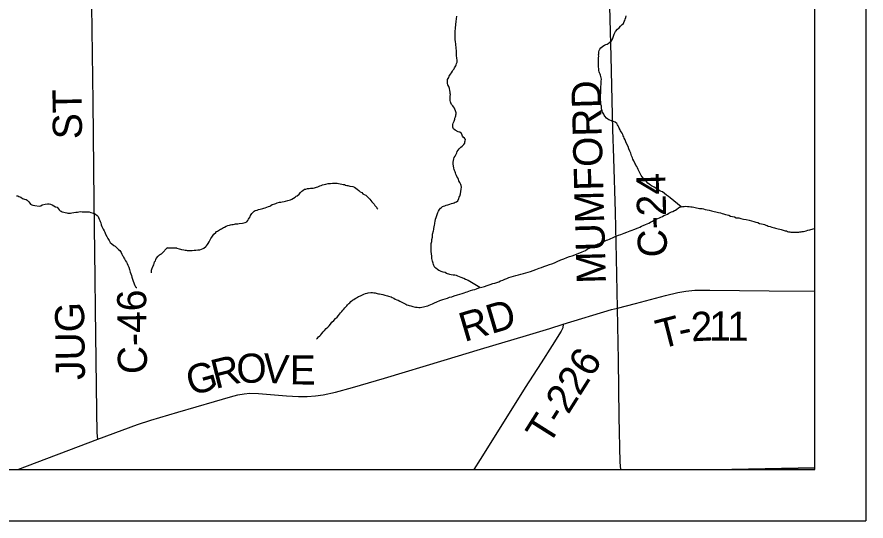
# Model space of a CAD drawing. Extents: x 0 to 34, y 0 to 22.
# Drawn here: x 7.606 to 9.262, y 14.238 to 15.221 of the extents above; entities that cross this region are included whole.
import ezdxf

# ---------------------------------------------------------------- set-up
doc = ezdxf.new("R2010")
doc.units = 0
for name, color, linetype in [('GM_X_Adjacent_County', 7, 'Continuous'), ('GM_X_County', 7, 'Continuous'), ('GM_X_County_Road', 7, 'Continuous'), ('GM_X_County_Road_Text', 7, 'Continuous'), ('GM_X_Minor_River', 7, 'Continuous'), ('GM_X_Township', 7, 'Continuous'), ('GM_X_Township_Road', 7, 'Continuous'), ('GM_X_Township_Road_Text', 7, 'Continuous'), ('SH_Data', 7, 'Continuous')]:
    doc.layers.add(name, color=color, linetype=linetype)

msp = doc.modelspace()

# ---------------------------------------------------------------- linework, layer by layer
at = {"layer": 'GM_X_Adjacent_County'}
msp.add_line((9.1622, 14.342), (9.0003, 14.3385), dxfattribs=at)
msp.add_lwpolyline([(9.0003, 14.3385), (9.1622, 14.3385), (9.1622, 14.342)], dxfattribs=at)
at = {"layer": 'GM_X_County'}
msp.add_line((9.0003, 14.3385), (9.1622, 14.342), dxfattribs=at)
msp.add_lwpolyline([(9.1622, 14.342), (9.1622, 21.1385), (2.3622, 21.1385), (2.3622, 14.3385), (9.0003, 14.3385)], dxfattribs=at)
at = {"layer": 'GM_X_County_Road'}
for points in [[(8.7838, 14.3385), (8.7824, 14.3532), (8.7805, 14.4411), (8.7792, 14.5521), (8.7772, 14.6534), (8.7751, 14.7509), (8.773, 14.8406), (8.7698, 14.9457), (8.7683, 15.0013), (8.7648, 15.1439), (8.7597, 15.3395), (8.7581, 15.4244), (8.756, 15.5234), (8.7553, 15.5899), (8.7512, 15.8644), (8.748, 16.0625), (8.7455, 16.2486), (8.7445, 16.3137), (8.7438, 16.3585)], [(7.7638, 14.3975), (7.7622, 14.4101), (7.7615, 14.4524), (7.7594, 14.6515), (7.7585, 14.7123), (7.7568, 14.8609), (7.7544, 15.0554), (7.7522, 15.2423), (7.7514, 15.2867), (7.7502, 15.4013), (7.7494, 15.4167)], [(7.6075, 14.3385), (7.7638, 14.3975)]]:
    msp.add_lwpolyline(points, dxfattribs=at)
at = {"layer": 'GM_X_Minor_River'}
for points in [[(8.4647, 14.9583), (8.4665, 14.9614), (8.4683, 14.9641), (8.4717, 14.9672), (8.4743, 14.9692), (8.4773, 14.9723), (8.4791, 14.975), (8.4794, 14.9773), (8.4801, 14.9796), (8.4809, 14.9823), (8.4785, 14.9845), (8.4762, 14.9868), (8.4746, 14.9886), (8.4742, 14.9905), (8.4726, 14.9939), (8.4699, 14.9961), (8.4664, 14.9968), (8.4603, 15.0001), (8.4572, 15.0031), (8.456, 15.0061), (8.4559, 15.0091), (8.4559, 15.011), (8.4565, 15.0141), (8.4584, 15.018), (8.4598, 15.0214), (8.4601, 15.0233), (8.4612, 15.026), (8.4616, 15.0279), (8.4619, 15.0298), (8.4622, 15.0321), (8.4622, 15.034), (8.4617, 15.0359), (8.4613, 15.0382), (8.4601, 15.0412), (8.4589, 15.0431), (8.457, 15.0457), (8.4558, 15.0476), (8.4534, 15.0502), (8.4518, 15.0536), (8.4514, 15.0555), (8.451, 15.0578), (8.4509, 15.0604), (8.4509, 15.0631), (8.4508, 15.0665), (8.4511, 15.0696), (8.451, 15.0715), (8.4506, 15.0741), (8.4501, 15.0775), (8.4493, 15.0817), (8.4481, 15.0855), (8.4465, 15.0889), (8.4453, 15.0911), (8.4455, 15.0988), (8.447, 15.1011), (8.448, 15.103), (8.4491, 15.1053), (8.4502, 15.1072), (8.4517, 15.1095), (8.4532, 15.1122), (8.455, 15.1153), (8.4568, 15.1177), (8.4583, 15.1196), (8.4594, 15.1215), (8.4605, 15.1235), (8.462, 15.1258), (8.4623, 15.1277), (8.4634, 15.1304), (8.4641, 15.1327), (8.4644, 15.135), (8.4644, 15.1369), (8.4639, 15.1403), (8.4635, 15.1422), (8.4631, 15.1444), (8.463, 15.1475), (8.4629, 15.1502), (8.4628, 15.1555), (8.4627, 15.1597), (8.4618, 15.1688), (8.4613, 15.1726), (8.4608, 15.1768), (8.4604, 15.1802), (8.4603, 15.1832), (8.4602, 15.1866), (8.4605, 15.1924), (8.4611, 15.1992), (8.462, 15.2061), (8.4627, 15.2118), (8.4633, 15.2175), (8.4636, 15.2225)], [(8.7409, 15.1529), (8.7412, 15.1556), (8.7427, 15.1583), (8.7449, 15.161), (8.7487, 15.1638), (8.7517, 15.1657), (8.7543, 15.1673), (8.7569, 15.1681), (8.7588, 15.1693), (8.7622, 15.1717), (8.7648, 15.1737), (8.7666, 15.176), (8.7681, 15.1798), (8.7691, 15.1833), (8.7698, 15.1852), (8.7706, 15.1871), (8.772, 15.1898), (8.7735, 15.1925), (8.7772, 15.1968), (8.7802, 15.1999), (8.7831, 15.203), (8.7861, 15.2061), (8.7887, 15.2084), (8.7902, 15.2119), (8.7913, 15.2138), (8.7923, 15.2169), (8.7934, 15.22), (8.7941, 15.223)], [(8.9011, 14.8508), (8.8798, 14.8686), (8.8763, 14.8712), (8.8724, 14.8738), (8.8686, 14.8768), (8.8647, 14.8797), (8.8601, 14.8815), (8.8574, 14.883), (8.8547, 14.8848), (8.8516, 14.887), (8.8485, 14.8893), (8.8458, 14.8903), (8.8435, 14.8918), (8.8412, 14.8933), (8.8389, 14.8947), (8.8361, 14.897), (8.8334, 14.9), (8.8299, 14.9033), (8.8276, 14.9063), (8.8252, 14.9093), (8.8232, 14.9119), (8.8185, 14.9209), (8.8173, 14.9236), (8.8161, 14.927), (8.8145, 14.9296), (8.8129, 14.9319), (8.8121, 14.9341), (8.8109, 14.936), (8.8089, 14.9405), (8.8073, 14.9435), (8.8061, 14.9465), (8.8045, 14.9503), (8.8029, 14.9552), (8.8009, 14.9594), (8.7992, 14.9639), (8.7976, 14.9684), (8.7956, 14.9726), (8.7936, 14.9775), (8.792, 14.9813), (8.7904, 14.9843), (8.7892, 14.9869), (8.788, 14.9892), (8.7872, 14.9918), (8.786, 14.9941), (8.7844, 14.9967), (8.7832, 14.999), (8.782, 15.0008), (8.7804, 15.0042), (8.7796, 15.0061), (8.7784, 15.0084), (8.7773, 15.0106), (8.7761, 15.0129), (8.7726, 15.0158), (8.7691, 15.0173), (8.7657, 15.0184), (8.7622, 15.0194), (8.7603, 15.0205), (8.758, 15.0216), (8.7557, 15.0238), (8.7525, 15.0272), (8.7513, 15.0295), (8.7502, 15.0313), (8.7478, 15.0355), (8.7473, 15.0377), (8.7465, 15.0396), (8.7461, 15.0415), (8.7457, 15.0449), (8.7456, 15.0468), (8.7452, 15.0491), (8.7447, 15.0518), (8.7443, 15.0548), (8.7442, 15.0594), (8.7437, 15.0635), (8.744, 15.0681), (8.7443, 15.0731), (8.7445, 15.0773), (8.7444, 15.0815), (8.7447, 15.0853), (8.745, 15.0891), (8.7453, 15.0921), (8.7453, 15.0959), (8.7456, 15.0994), (8.7451, 15.102), (8.7447, 15.1047), (8.7439, 15.1073), (8.743, 15.1096), (8.7422, 15.1119), (8.7414, 15.1141), (8.741, 15.1168), (8.7405, 15.1198), (8.7401, 15.1236), (8.74, 15.1278), (8.7399, 15.132), (8.7402, 15.1362), (8.7401, 15.1388), (8.74, 15.1415), (8.7404, 15.1442), (8.7403, 15.1468), (8.7406, 15.1491), (8.7406, 15.151), (8.7409, 15.1529)], [(8.5085, 14.6935), (8.4856, 14.7072), (8.4833, 14.7083), (8.4806, 14.7093), (8.4772, 14.7108), (8.4722, 14.7133), (8.4687, 14.7144), (8.466, 14.7155), (8.4633, 14.7166), (8.4599, 14.7173), (8.4565, 14.7176), (8.453, 14.7182), (8.4504, 14.7186), (8.4435, 14.7207), (8.4408, 14.7225), (8.4369, 14.7232), (8.435, 14.7239), (8.4331, 14.725), (8.4308, 14.7261), (8.4285, 14.7268), (8.4258, 14.7287), (8.4227, 14.7309), (8.4208, 14.7324), (8.4191, 14.7361), (8.4183, 14.7384), (8.4175, 14.7407), (8.4163, 14.7448), (8.4155, 14.7475), (8.415, 14.7498), (8.4149, 14.7547), (8.4144, 14.7593), (8.414, 14.7638), (8.4135, 14.7672), (8.4134, 14.7707), (8.4134, 14.7733), (8.4137, 14.7756), (8.414, 14.779), (8.4147, 14.7829), (8.4153, 14.7871), (8.416, 14.7913), (8.4166, 14.7974), (8.4184, 14.8039), (8.4187, 14.8066), (8.419, 14.8085), (8.4197, 14.8119), (8.4204, 14.815), (8.4207, 14.8176), (8.421, 14.8196), (8.4214, 14.8222), (8.422, 14.8264), (8.4235, 14.8299), (8.426, 14.8376), (8.427, 14.8399), (8.4281, 14.8422), (8.43, 14.8456), (8.4322, 14.8484), (8.4341, 14.8495), (8.4359, 14.8511), (8.4378, 14.8519), (8.4401, 14.8527), (8.4427, 14.8539), (8.4461, 14.8548), (8.4499, 14.856), (8.4533, 14.8572), (8.4563, 14.858), (8.4586, 14.8588), (8.4608, 14.86), (8.4631, 14.8605), (8.4657, 14.8624), (8.4675, 14.8667), (8.4686, 14.8697), (8.4693, 14.8716), (8.4707, 14.8762), (8.4718, 14.8808), (8.472, 14.885), (8.4727, 14.8888), (8.4719, 14.8923), (8.4715, 14.8941), (8.4695, 14.8979), (8.4675, 14.9017), (8.4667, 14.9039), (8.4654, 14.9073), (8.4639, 14.9096), (8.4631, 14.9119), (8.4619, 14.9145), (8.461, 14.9168), (8.4602, 14.919), (8.4594, 14.9213), (8.4586, 14.9236), (8.4582, 14.9262), (8.4568, 14.9349), (8.4568, 14.938), (8.4571, 14.941), (8.4581, 14.9445), (8.4588, 14.9468), (8.4607, 14.9495), (8.4618, 14.9522), (8.4636, 14.956), (8.4647, 14.9583)], [(7.9178, 14.7702), (7.8991, 14.7705), (7.9178, 14.7702), (7.922, 14.7688), (7.9251, 14.7685), (7.927, 14.7678), (7.9312, 14.7667), (7.9339, 14.7664), (7.9358, 14.7661), (7.9381, 14.7657), (7.9408, 14.7658), (7.943, 14.7658), (7.9453, 14.7659), (7.9476, 14.7659), (7.9518, 14.766), (7.9548, 14.7665), (7.9586, 14.7666), (7.9609, 14.7666), (7.9628, 14.7667), (7.9658, 14.7683), (7.9688, 14.7695), (7.9707, 14.7699), (7.9741, 14.7734), (7.9759, 14.775), (7.9778, 14.7773), (7.9789, 14.7792), (7.9807, 14.7823), (7.9825, 14.7861), (7.984, 14.7892), (7.9862, 14.7919), (7.9884, 14.7954), (7.9902, 14.7974), (7.9936, 14.8005), (7.9951, 14.8024), (7.9973, 14.8036), (8.0007, 14.806), (8.0029, 14.8072), (8.0048, 14.808), (8.0071, 14.8092), (8.009, 14.8103), (8.0108, 14.8111), (8.0142, 14.8131), (8.0169, 14.8143), (8.0203, 14.8152), (8.0225, 14.8156), (8.0248, 14.816), (8.0275, 14.8165), (8.0301, 14.8169), (8.032, 14.8173), (8.0343, 14.8174), (8.0366, 14.8178), (8.0392, 14.8182), (8.0457, 14.8192), (8.0487, 14.8196), (8.0513, 14.82), (8.054, 14.8212), (8.0562, 14.8243), (8.0577, 14.8267), (8.0591, 14.8286), (8.0606, 14.8313), (8.0617, 14.8336), (8.0624, 14.8355), (8.0639, 14.8378), (8.0668, 14.8406), (8.0687, 14.8421), (8.0706, 14.8433), (8.0744, 14.8445), (8.077, 14.8454), (8.08, 14.8462), (8.083, 14.847), (8.0853, 14.8474), (8.0872, 14.8483), (8.0902, 14.8491), (8.0932, 14.8503), (8.0963, 14.8515), (8.0989, 14.8523), (8.1012, 14.8535), (8.1034, 14.8551), (8.1064, 14.8559), (8.1087, 14.8567), (8.1106, 14.8575), (8.1136, 14.8587), (8.1178, 14.8596), (8.1204, 14.86), (8.1234, 14.8605), (8.1269, 14.8609), (8.1299, 14.8621), (8.134, 14.863), (8.1371, 14.8638), (8.1393, 14.8646), (8.1423, 14.8659), (8.1487, 14.8698), (8.1506, 14.8714), (8.1525, 14.8725), (8.1562, 14.8757), (8.1588, 14.8784), (8.1614, 14.8815), (8.1633, 14.8827), (8.1666, 14.885), (8.1693, 14.8855)], [(8.1693, 14.8855), (8.1727, 14.8863), (8.1761, 14.8868), (8.1784, 14.8872), (8.1814, 14.8873), (8.1833, 14.8873), (8.186, 14.8878), (8.1901, 14.889), (8.1924, 14.8898), (8.1965, 14.8914), (8.1992, 14.8922), (8.2018, 14.8934), (8.2048, 14.8943), (8.2086, 14.8951), (8.2128, 14.896), (8.2173, 14.8965), (8.2211, 14.8969), (8.2242, 14.897), (8.2268, 14.8971), (8.2306, 14.8971), (8.2333, 14.8964), (8.2364, 14.8957), (8.2394, 14.8951), (8.2421, 14.8943), (8.2444, 14.894), (8.2467, 14.8933), (8.249, 14.8926), (8.2513, 14.8923), (8.2532, 14.8916), (8.2551, 14.8912), (8.2608, 14.8902), (8.2639, 14.8891), (8.267, 14.8873), (8.2693, 14.8851), (8.2724, 14.8825), (8.2755, 14.8802), (8.2786, 14.8784), (8.2805, 14.8762), (8.2832, 14.8751), (8.2863, 14.8733), (8.289, 14.8707), (8.2918, 14.8684), (8.2941, 14.8654), (8.2961, 14.8632), (8.298, 14.8606), (8.3004, 14.858), (8.3023, 14.8557), (8.3039, 14.8535), (8.3066, 14.8505), (8.307, 14.8501), (8.3078, 14.8482), (8.3098, 14.8464)], [(7.6052, 14.8725), (7.6075, 14.8722), (7.6094, 14.8711), (7.6133, 14.8693)], [(7.6133, 14.8693), (7.6167, 14.867), (7.6209, 14.8656), (7.624, 14.8649), (7.6259, 14.8635), (7.6291, 14.8605), (7.631, 14.8579), (7.6326, 14.856), (7.6349, 14.8549), (7.6372, 14.8538), (7.641, 14.8531), (7.6494, 14.8522), (7.6524, 14.853), (7.6551, 14.8546), (7.6607, 14.8559), (7.6653, 14.8567), (7.6687, 14.8564), (7.6714, 14.8557), (7.6745, 14.8547), (7.6779, 14.8525), (7.6814, 14.8506), (7.6845, 14.8499), (7.6861, 14.8473), (7.688, 14.8447), (7.6899, 14.8432), (7.6919, 14.8425), (7.6942, 14.841), (7.6972, 14.8403), (7.6999, 14.8396), (7.703, 14.8389), (7.7053, 14.8386), (7.7079, 14.8387), (7.7102, 14.8387), (7.7129, 14.8388), (7.7167, 14.8396), (7.7208, 14.8401), (7.7243, 14.8406), (7.7269, 14.841), (7.7307, 14.8415), (7.7334, 14.8412), (7.736, 14.8412), (7.7402, 14.8413), (7.7436, 14.841), (7.7467, 14.8407), (7.7498, 14.84), (7.7544, 14.8386), (7.757, 14.8379), (7.7594, 14.8364), (7.7625, 14.8338), (7.7644, 14.8316), (7.7652, 14.8297), (7.7664, 14.8267), (7.7676, 14.8244), (7.7684, 14.8222), (7.7693, 14.8195), (7.7701, 14.8154), (7.7717, 14.8127), (7.7729, 14.8101), (7.7741, 14.8075), (7.7757, 14.8041), (7.7773, 14.8011), (7.7789, 14.7977), (7.7809, 14.7931), (7.7833, 14.789), (7.7856, 14.7853), (7.788, 14.7815), (7.7911, 14.7785), (7.795, 14.7756), (7.7973, 14.7741), (7.7996, 14.7723), (7.8016, 14.7704), (7.8039, 14.7678), (7.8063, 14.7656), (7.8078, 14.7637), (7.8094, 14.7614), (7.8106, 14.7588), (7.8118, 14.7562), (7.813, 14.7543), (7.8142, 14.7513), (7.8158, 14.7494), (7.8177, 14.7457), (7.8193, 14.743), (7.8209, 14.7404), (7.8221, 14.737), (7.8241, 14.7329), (7.8257, 14.7283), (7.827, 14.7234), (7.8282, 14.72), (7.8291, 14.717), (7.8303, 14.7136), (7.8324, 14.7057), (7.8336, 14.7026), (7.8348, 14.7004), (7.8356, 14.6977), (7.8372, 14.6951), (7.8379, 14.6947), (7.8387, 14.6936), (7.8395, 14.6933)], [(8.8646, 14.8321), (8.8672, 14.8341), (8.8714, 14.8353), (8.8744, 14.8365), (8.877, 14.8381), (8.8797, 14.8397), (8.8827, 14.8409), (8.8849, 14.8417), (8.888, 14.8433), (8.8902, 14.8445), (8.8928, 14.8465), (8.8958, 14.8488), (8.8981, 14.85), (8.9011, 14.8508), (8.9037, 14.8513), (8.9068, 14.8517), (8.9102, 14.8518), (8.9136, 14.8515), (8.9171, 14.8512), (8.9201, 14.8509), (8.9228, 14.8506), (8.9258, 14.8499), (8.9285, 14.8492), (8.9312, 14.8488), (8.9342, 14.8482), (8.9373, 14.8478), (8.9419, 14.8472), (8.9445, 14.8469), (8.948, 14.8458), (8.9518, 14.8451), (8.9556, 14.8441), (8.9602, 14.843), (8.974, 14.8395), (8.9778, 14.8388), (8.9809, 14.8378), (8.9836, 14.8371), (8.9874, 14.836), (8.9908, 14.8353), (8.9939, 14.8343), (8.9977, 14.8328), (9.0015, 14.8321), (9.005, 14.8311), (9.0088, 14.8296), (9.0134, 14.829), (9.0176, 14.8279), (9.0226, 14.8269), (9.0279, 14.8259), (9.0341, 14.8245), (9.0383, 14.8235), (9.0429, 14.822), (9.0467, 14.821), (9.0505, 14.8199), (9.0543, 14.8185), (9.0578, 14.8178), (9.0609, 14.8167), (9.0635, 14.816), (9.0662, 14.8153), (9.0689, 14.8142), (9.0712, 14.8131), (9.075, 14.8121), (9.0781, 14.8114), (9.0804, 14.8107), (9.0831, 14.81), (9.0854, 14.8093), (9.088, 14.8086), (9.0907, 14.8079), (9.0938, 14.8072), (9.0961, 14.8065), (9.098, 14.8061), (9.0999, 14.8054), (9.1022, 14.8047), (9.1041, 14.804), (9.1068, 14.8037), (9.1087, 14.8029), (9.1106, 14.8022), (9.1129, 14.8019), (9.1152, 14.8016), (9.1171, 14.8012), (9.1205, 14.8013), (9.124, 14.8014), (9.1308, 14.8015), (9.1327, 14.802), (9.135, 14.802), (9.1372, 14.8024), (9.1399, 14.8029), (9.1422, 14.8033), (9.1448, 14.8041), (9.1482, 14.805), (9.152, 14.8058), (9.1584, 14.8079), (9.1622, 14.8088)], [(8.4495, 14.6744), (8.454, 14.6756), (8.4585, 14.6773), (8.4649, 14.6793), (8.4695, 14.6805), (8.474, 14.6818), (8.4778, 14.683), (8.4812, 14.6842), (8.4842, 14.6851), (8.4872, 14.6863), (8.4906, 14.6875), (8.4948, 14.6887), (8.4986, 14.6899), (8.5023, 14.6912), (8.5065, 14.6928), (8.5125, 14.6944), (8.5178, 14.6957), (8.5231, 14.6977), (8.5288, 14.6994), (8.5341, 14.701), (8.5378, 14.7022), (8.5416, 14.7035), (8.5454, 14.7047), (8.5491, 14.7063), (8.5533, 14.7079), (8.5571, 14.7095), (8.5616, 14.7112), (8.5654, 14.7128), (8.5695, 14.714), (8.574, 14.7156), (8.579, 14.7169), (8.5839, 14.7181), (8.5888, 14.7198), (8.5937, 14.721), (8.5982, 14.7223), (8.6028, 14.7235), (8.6073, 14.7247), (8.6179, 14.7288), (8.6209, 14.73), (8.6246, 14.7312), (8.6288, 14.7328), (8.6337, 14.7345), (8.6394, 14.7365), (8.6446, 14.7381), (8.6492, 14.7398), (8.6541, 14.7418), (8.6593, 14.7442), (8.6669, 14.7474), (8.6725, 14.7494), (8.6786, 14.7518), (8.6838, 14.7539), (8.6887, 14.7555), (8.6936, 14.7575), (8.6986, 14.7591), (8.7035, 14.7612), (8.708, 14.7628), (8.7117, 14.7644), (8.7148, 14.7656), (8.7181, 14.7679), (8.7238, 14.7707), (8.7279, 14.7727), (8.7321, 14.7743), (8.7339, 14.7752), (8.7369, 14.7771), (8.7392, 14.7783), (8.7418, 14.7795), (8.7452, 14.7815), (8.7486, 14.7827), (8.7516, 14.7839), (8.7554, 14.7855), (8.7584, 14.7867), (8.7614, 14.7879), (8.7644, 14.7892), (8.7674, 14.7904), (8.7701, 14.7916), (8.7727, 14.7928), (8.7757, 14.794), (8.7791, 14.7952), (8.7833, 14.7968), (8.787, 14.798), (8.7904, 14.7996), (8.7953, 14.8013), (8.7987, 14.8025), (8.8021, 14.8041), (8.8059, 14.8053), (8.8089, 14.8065), (8.8176, 14.8101), (8.8206, 14.8114), (8.824, 14.8129), (8.827, 14.8142), (8.8315, 14.8162), (8.8349, 14.8174), (8.8383, 14.819), (8.8413, 14.8206), (8.8451, 14.8226), (8.8484, 14.8245), (8.8526, 14.8265), (8.856, 14.8281), (8.859, 14.8293), (8.8616, 14.8309), (8.8646, 14.8321)], [(7.8681, 14.7221), (7.8684, 14.7274), (7.8698, 14.7309), (7.8705, 14.7328), (7.8716, 14.7355), (7.8731, 14.7378), (7.8734, 14.7401), (7.8745, 14.7435), (7.876, 14.7458), (7.8767, 14.7481), (7.8774, 14.7501), (7.8811, 14.7543), (7.8837, 14.757), (7.8859, 14.7582), (7.8878, 14.7594), (7.8886, 14.7598), (7.8893, 14.7602), (7.8991, 14.7705)], [(8.1903, 14.5931), (8.1923, 14.5948), (8.1941, 14.5971), (8.1963, 14.5994), (8.1986, 14.6014), (8.2004, 14.6037), (8.203, 14.6068), (8.206, 14.6099), (8.209, 14.6134), (8.2119, 14.6162), (8.2145, 14.6189), (8.2175, 14.622), (8.2201, 14.6259), (8.2238, 14.6294), (8.2271, 14.6329), (8.2301, 14.6356), (8.2327, 14.6387), (8.2349, 14.6414), (8.2372, 14.6441), (8.2394, 14.6465), (8.2412, 14.6492), (8.2435, 14.6515), (8.2453, 14.6538), (8.249, 14.6577), (8.2505, 14.66), (8.2531, 14.6624), (8.255, 14.6639), (8.2572, 14.6659), (8.2606, 14.6686), (8.2632, 14.6702), (8.2658, 14.6718), (8.2681, 14.6734), (8.2699, 14.6746), (8.2718, 14.6757), (8.2737, 14.6765), (8.2756, 14.6774), (8.2775, 14.6782), (8.2808, 14.6798), (8.2827, 14.6806), (8.2857, 14.6818), (8.2888, 14.6826), (8.291, 14.683), (8.296, 14.6835), (8.299, 14.6836), (8.3021, 14.6833), (8.3044, 14.6829), (8.3063, 14.6822), (8.3082, 14.6819), (8.3109, 14.6812), (8.3132, 14.6809), (8.3162, 14.6805), (8.3193, 14.6799), (8.3212, 14.6795), (8.3231, 14.6788), (8.3258, 14.6781), (8.3284, 14.6774), (8.3307, 14.6767), (8.3334, 14.676), (8.3357, 14.6753), (8.3376, 14.6742), (8.3407, 14.6727), (8.3438, 14.6709), (8.3469, 14.6694), (8.3492, 14.6687), (8.3523, 14.6669), (8.3542, 14.6662), (8.3565, 14.6651), (8.3592, 14.6636), (8.3627, 14.6618), (8.3646, 14.6611), (8.3665, 14.66), (8.3688, 14.6593), (8.3707, 14.6585), (8.3738, 14.6575), (8.3757, 14.6571), (8.378, 14.6564), (8.3807, 14.6557), (8.3833, 14.6554), (8.3864, 14.6551), (8.3894, 14.6548), (8.3921, 14.6548), (8.3989, 14.6557), (8.4016, 14.6562), (8.4042, 14.657), (8.4069, 14.6578), (8.4095, 14.659), (8.4133, 14.6606), (8.4163, 14.6618), (8.42, 14.6638), (8.4249, 14.6658), (8.4306, 14.6683), (8.4363, 14.6699), (8.4408, 14.6711), (8.4453, 14.6728), (8.4495, 14.6744)]]:
    msp.add_lwpolyline(points, dxfattribs=at)
at = {"layer": 'GM_X_Township'}
for p, q in [((9.1622, 14.342), (9.1622, 19.7691)), ((9.0003, 14.3385), (9.1622, 14.342)), ((4.4492, 14.3385), (9.0003, 14.3385))]:
    msp.add_line(p, q, dxfattribs=at)
at = {"layer": 'GM_X_Township_Road'}
for points in [[(8.7772, 14.6534), (8.812, 14.6623), (8.8709, 14.6776), (8.8946, 14.6836), (8.9104, 14.6864), (8.9279, 14.6883), (8.9574, 14.6885), (9.073, 14.6871), (9.1611, 14.6862), (9.1622, 14.6862)], [(7.7638, 14.3975), (7.811, 14.4152), (7.8408, 14.4262), (7.8673, 14.4348), (7.9197, 14.4502), (7.991, 14.471), (8.0226, 14.4806), (8.0365, 14.484), (8.0493, 14.4862), (8.0603, 14.4872), (8.0767, 14.4869), (8.1002, 14.4847), (8.1313, 14.4825), (8.1549, 14.4813), (8.1722, 14.4813), (8.1884, 14.4823), (8.2033, 14.484), (8.2271, 14.4894), (8.2604, 14.4987), (8.3229, 14.5166), (8.4391, 14.5519), (8.51, 14.5731), (8.5999, 14.5996), (8.645, 14.6133), (8.6714, 14.6221), (8.7654, 14.6508), (8.7772, 14.6534)], [(8.6714, 14.6221), (8.6702, 14.6148), (8.6675, 14.6082), (8.6496, 14.5802), (8.6281, 14.5467), (8.597, 14.4984), (8.5564, 14.4329), (8.5095, 14.3581), (8.4971, 14.3385)]]:
    msp.add_lwpolyline(points, dxfattribs=at)
at = {"layer": 'SH_Data'}
for p in [(9.2617, 21.2383), (2.2617, 14.2383)]:
    msp.add_line(p, (9.2617, 14.2383), dxfattribs=at)

# ---------------------------------------------------------------- texts
at = {"layer": 'GM_X_County_Road_Text'}
for s, rotation, p in [('MUMFORD', 91.5871, (8.7546, 14.7015)), ('ST', 90.5903, (7.7329, 14.9828)), ('C-24', 91.3645, (8.874, 14.7529)), ('C-46', 90.6871, (7.8598, 14.525)), ('JUG', 90.7499, (7.7387, 14.5136))]:
    msp.add_text(s, height=0.05682, rotation=rotation, dxfattribs=at).set_placement(p)
at = {"layer": 'GM_X_Township_Road_Text'}
for s, height, rotation, p in [('RD', 0.05682, 16.4164, (8.4783, 14.587)), ('T', 0.0568, 14.3699, (8.8607, 14.5734)), ('2', 0.0568, 2.8424, (8.9216, 14.5884)), ('1', 0.0568, 359.6826, (8.9558, 14.5901)), ('1', 0.0568, 359.3963, (8.9907, 14.5899)), ('-', 0.0568, 12.1275, (8.9012, 14.5838)), ('T-226', 0.05682, 57.7874, (8.6429, 14.3838)), ('R', 0.0568, 14.111, (7.9929, 14.4954)), ('O', 0.0568, 3.0248, (8.0353, 14.5063)), ('V', 0.0568, 355.1641, (8.0831, 14.509)), ('E', 0.0568, 359.5325, (8.1377, 14.5046)), ('G', 0.0568, 15.5516, (7.9451, 14.4821))]:
    msp.add_text(s, height=height, rotation=rotation, dxfattribs=at).set_placement(p)

doc.saveas('drawing.dxf')
